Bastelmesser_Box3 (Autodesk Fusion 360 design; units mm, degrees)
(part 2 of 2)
sketch "Skizze4" plane through (0, 0, 22) normal (0, 0, -1) x axis (1, 0, 0)
  line L1 (-74.6486, 4.3998) -> (74.6267, 4.3982)
  line L2 (-75.4335, 4.1218) -> (-74.6486, 4.3998)
  line L3 (-76.2604, 3.6728) -> (-75.4335, 4.1218)
  line L4 (-77.0079, 3.099) -> (-76.2604, 3.6728)
  line L5 (-77.6547, 2.4173) -> (-77.0079, 3.099)
  line L6 (-78.1871, 1.6426) -> (-77.6547, 2.4173)
  line L7 (-78.5922, 0.7932) -> (-78.1871, 1.6426)
  line L8 (-78.8596, -0.1097) -> (-78.5922, 0.7932)
  line L9 (-78.9823, -1.0422) -> (-78.8596, -0.1097)
  line L10 (-78.986, -28.0662) -> (-78.9823, -1.0422)
  line L11 (-78.9923, -28.0662) -> (-78.986, -28.0662)
  line L12 (-78.9946, -45.3556) -> (-78.9923, -28.0662)
  line L13 (-78.9578, -45.9816) -> (-78.9946, -45.3556)
  line L14 (-78.7863, -46.9071) -> (-78.9578, -45.9816)
  line L15 (-78.4721, -47.7945) -> (-78.7863, -46.9071)
  line L16 (-78.0231, -48.6214) -> (-78.4721, -47.7945)
  line L17 (-77.4515, -49.3665) -> (-78.0231, -48.6214)
  line L18 (-76.7688, -50.0146) -> (-77.4515, -49.3665)
  line L19 (-75.9928, -50.5481) -> (-76.7688, -50.0146)
  line L20 (-75.1435, -50.9532) -> (-75.9928, -50.5481)
  line L21 (-74.2406, -51.2206) -> (-75.1435, -50.9532)
  line L22 (-73.3081, -51.3433) -> (-74.2406, -51.2206)
  line L23 (73.0054, -51.3556) -> (-73.3081, -51.3433)
  line L24 (73.6314, -51.3188) -> (73.0054, -51.3556)
  line L25 (74.5569, -51.1473) -> (73.6314, -51.3188)
  line L26 (75.4442, -50.8331) -> (74.5569, -51.1473)
  line L27 (76.2712, -50.3841) -> (75.4442, -50.8331)
  line L28 (77.0186, -49.8103) -> (76.2712, -50.3841)
  line L29 (77.6654, -49.1285) -> (77.0186, -49.8103)
  line L30 (78.1978, -48.3538) -> (77.6654, -49.1285)
  line L31 (78.603, -47.5045) -> (78.1978, -48.3538)
  line L32 (78.8704, -46.6016) -> (78.603, -47.5045)
  line L33 (78.9931, -45.6691) -> (78.8704, -46.6016)
  line L34 (78.9954, -28.0662) -> (78.9931, -45.6691)
  line L35 (79.0018, -28.0662) -> (78.9954, -28.0662)
  line L36 (79.0054, -1.3556) -> (79.0018, -28.0662)
  line L37 (78.9685, -0.7297) -> (79.0054, -1.3556)
  line L38 (78.797, 0.1959) -> (78.9685, -0.7297)
  line L39 (78.4828, 1.0832) -> (78.797, 0.1959)
  line L40 (78.0338, 1.9102) -> (78.4828, 1.0832)
  line L41 (77.4622, 2.6553) -> (78.0338, 1.9102)
  line L42 (76.7795, 3.3034) -> (77.4622, 2.6553)
  line L43 (76.0036, 3.8368) -> (76.7795, 3.3034)
  line L44 (75.1543, 4.242) -> (76.0036, 3.8368)
  line L45 (74.6267, 4.3982) -> (75.1543, 4.242)
  line L46 (73.2524, 2.3821) -> (4.5274, 2.3878)
  line L47 (76.7518, -28.0662) -> (76.7554, -1.3636)
  line L48 (76.7454, -28.0662) -> (76.7518, -28.0662)
  line L49 (76.7431, -45.6026) -> (76.7454, -28.0662)
  line L50 (-73.2416, -49.0933) -> (72.9975, -49.1056)
  line L51 (-76.7423, -28.0662) -> (-76.7446, -45.3477)
  line L52 (-76.736, -28.0662) -> (-76.7423, -28.0662)
  line L53 (-76.7323, -1.1087) -> (-76.736, -28.0662)
  line L54 (-4.4801, 2.3886) -> (-72.9867, 2.3944)
  line L55 (-4.6241, 3.499) -> (-4.6241, 2.399)
  line L56 (4.6759, 3.4989) -> (-4.6241, 3.499)
  line L57 (4.6759, 2.3989) -> (4.6759, 3.4989)
  line L58 (3.6759, 1.3989) -> (3.6759, 0.4365)
  line L59 (4.6759, 3.4989) -> (4.6759, 2.3989)
  line L60 (-4.6241, 3.499) -> (4.6759, 3.4989)
  line L61 (-4.6241, 2.399) -> (-4.6241, 3.499)
  line L62 (-3.6241, 0.4365) -> (-3.6241, 1.399)
  line L63 (-76.111, 2.359) -> (-75.7926, 2.6225)
  line L64 (-76.8834, 1.5652) -> (-76.7298, 1.7396)
  line L65 (-77.2915, 0.9221) -> (-76.8834, 1.5652)
  line L66 (-77.5943, 0.2226) -> (-77.2915, 0.9221)
  line L67 (-77.7838, -0.516) -> (-77.5943, 0.2226)
  line L68 (-77.8485, -1.2003) -> (-77.7838, -0.516)
  line L69 (-77.8485, -4.8869) -> (-77.8485, -1.2003)
  line L70 (-76.7485, -4.8869) -> (-77.8485, -4.8869)
  line L71 (-74.202, -3.8821) -> (-75.7516, -3.8869)
  line L72 (-70.4875, 1.3992) -> (-70.4868, -0.1536)
  line L73 (-69.4875, 3.4997) -> (-69.4875, 2.3997)
  line L74 (-73.0871, 3.4997) -> (-69.4875, 3.4997)
  line L75 (-73.6968, 3.4545) -> (-73.0871, 3.4997)
  line L76 (-74.4278, 3.2911) -> (-73.6968, 3.4545)
  line L77 (-75.1365, 3.0105) -> (-74.4278, 3.2911)
  line L78 (-75.7926, 2.6225) -> (-75.1365, 3.0105)
  line L79 (75.7523, -3.8661) -> (74.2621, -3.8625)
  line L80 (77.8499, -4.8661) -> (76.7499, -4.8661)
  line L81 (77.85, -1.2631) -> (77.8499, -4.8661)
  line L82 (77.8047, -0.6535) -> (77.85, -1.2631)
  line L83 (77.6414, 0.0776) -> (77.8047, -0.6535)
  line L84 (77.3608, 0.7863) -> (77.6414, 0.0776)
  line L85 (76.9729, 1.442) -> (77.3608, 0.7863)
  line L86 (76.8724, 1.5635) -> (76.9729, 1.442)
  line L87 (75.9161, 2.5327) -> (76.2518, 2.2367)
  line L88 (75.2724, 2.9413) -> (75.9161, 2.5327)
  line L89 (74.5729, 3.244) -> (75.2724, 2.9413)
  line L90 (73.8343, 3.4336) -> (74.5729, 3.244)
  line L91 (73.1499, 3.4982) -> (73.8343, 3.4336)
  line L92 (69.6287, 3.4982) -> (73.1499, 3.4982)
  line L93 (69.6287, 2.3982) -> (69.6287, 3.4982)
  line L94 (70.6209, -0.1946) -> (70.6287, 1.3933)
  arc A1 centre (4.6759, 1.3989) radius 1 clockwise from (4.5274, 2.3878) to (4.6759, 2.3989)
  arc A2 centre (73.0018, -1.3631) radius 3.7536 clockwise from (73.2524, 2.3821) to (76.7554, -1.3636)
  arc A3 centre (72.9978, -45.352) radius 3.7537 clockwise from (76.7431, -45.6026) to (72.9975, -49.1056)
  arc A4 centre (-72.9911, -45.3482) radius 3.7536 clockwise from (-73.2416, -49.0933) to (-76.7446, -45.3477)
  arc A5 centre (-72.987, -1.3593) radius 3.7537 clockwise from (-76.7323, -1.1087) to (-72.9867, 2.3944)
  arc A6 centre (-4.6241, 1.399) radius 1 clockwise from (-4.6241, 2.399) to (-4.4801, 2.3886)
  circle C1 centre (0.0259, 0.4365) radius 3.05
  arc A7 centre (4.6759, 1.3989) radius 1 clockwise from (3.6759, 1.3989) to (4.6759, 2.3989)
  arc A8 centre (-4.6241, 1.399) radius 1 clockwise from (-4.6241, 2.399) to (-3.6241, 1.399)
  arc A9 centre (0.0259, 0.4365) radius 3.65 clockwise from (3.6759, 0.4365) to (-3.6241, 0.4365)
  arc A10 centre (-74.2135, -0.1554) radius 3.15 clockwise from (-76.111, 2.359) to (-76.7298, 1.7396)
  arc A11 centre (-75.7485, -4.8869) radius 1 clockwise from (-76.7485, -4.8869) to (-75.7516, -3.8869)
  arc A12 centre (-74.2135, -0.1554) radius 3.7267 clockwise from (-70.4868, -0.1536) to (-74.202, -3.8821)
  arc A13 centre (-69.4875, 1.3997) radius 1 clockwise from (-70.4875, 1.3992) to (-69.4875, 2.3997)
  arc A14 centre (75.7499, -4.8661) radius 1 clockwise from (75.7523, -3.8661) to (76.7499, -4.8661)
  arc A15 centre (74.2708, -0.2125) radius 3.15 clockwise from (76.8724, 1.5635) to (76.2518, 2.2367)
  arc A16 centre (69.6287, 1.3982) radius 1 clockwise from (69.6287, 2.3982) to (70.6287, 1.3933)
  arc A17 centre (74.2708, -0.2125) radius 3.65 clockwise from (74.2621, -3.8625) to (70.6209, -0.1946)
  circle C2 centre (74.2708, -0.2125) radius 3.15
  circle C3 centre (-74.2135, -0.1554) radius 3.15
  point P115 (76.8724, 1.5635)
  point P83 (-76.111, 2.359)
  concentric A15 C2
  coincident P115 C2
  concentric A10 C3
  coincident P83 C3
extrude "Extrusion2" cut sketch "Skizze4" profile of L46 L47 L48 L49 A3 L50 A4 L51 L52 L53 A5 L54 L58 A7 A8 L62 A9 A10 A11 L71 A12 L72 A13 L79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 against normal blind 1.213
extrude "Extrusion3" cut of existing geometry blind -2.287
extrude "Extrusion4" cut sketch "Skizze4" profile of L46 A2 L47 A15 C2 against normal blind 3.452
combine "Kombinieren2"
extrude "Extrusion11" new body of existing geometry blind 3.5
extrude "Extrusion12" cut of existing geometry blind -2.05
extrude "Extrusion13" new body of existing geometry blind 3.452
extrude "Extrusion14" new body of existing geometry blind 3.5
combine "Kombinieren2"
extrude "Extrusion15" cut of existing geometry blind -2.05
extrude "Extrusion16" new body of existing geometry blind 3.5
delete_face "Fläche löschen3"
extrude "Extrusion17" new body of existing geometry blind 3.5
combine "Kombinieren3"
extrude "Extrusion18" cut of existing geometry blind -2.05
fillet "Abrundung1" radius 2
combine "Kombinieren3"
extrude "Extrusion5" cut of existing geometry blind -0.006
sketch "Skizze5" plane through (0, 0, 25.5) normal (0, 0, -1) x axis (1, 0, 0)
  line L1 (74.755, -3.8637) -> (74.7518, -28.0662)
  line L2 (74.2621, -3.8625) -> (74.755, -3.8637)
  line L3 (70.6237, 0.3823) -> (70.6209, -0.1946)
  line L4 (3.6755, 0.3879) -> (70.6237, 0.3823)
  line L5 (-70.487, 0.3942) -> (-3.6238, 0.3885)
  line L6 (-70.4868, -0.1536) -> (-70.487, 0.3942)
  line L7 (-74.739, -3.8838) -> (-74.202, -3.8821)
  line L8 (-74.7446, -45.3479) -> (-74.739, -3.8838)
  line L9 (72.9976, -47.1056) -> (-73.1622, -47.0933)
  line L10 (74.7454, -28.0662) -> (74.7431, -45.523)
  line L11 (74.7518, -28.0662) -> (74.7454, -28.0662)
  line L12 (-0.0823, -47.0995) -> (0, 0)
  arc A1 centre (74.2708, -0.2125) radius 3.65 clockwise from (74.2621, -3.8625) to (70.6209, -0.1946)
  arc A2 centre (0.0259, 0.4365) radius 3.65 clockwise from (3.6755, 0.3879) to (-3.6238, 0.3885)
  arc A3 centre (-74.2135, -0.1554) radius 3.7267 clockwise from (-70.4868, -0.1536) to (-74.202, -3.8821)
  arc A4 centre (-72.9911, -45.3482) radius 1.7535 clockwise from (-73.1622, -47.0933) to (-74.7446, -45.3479)
  arc A5 centre (72.9978, -45.352) radius 1.7537 clockwise from (74.7431, -45.523) to (72.9976, -47.1056)
  circle C1 centre (-0.0411, -23.5497) radius 3.1
  circle C2 centre (-0.0411, -23.5497) radius 4
  point P1 (0, 0)
  point P23 (0, 0)
  point P24 (-0.0823, -47.0995)
  point P25 (-0.0411, -23.5497)
  point P27 (-0.0411, -23.5497)
  coincident P1 P23
  midpoint L9 P24
  midpoint L12 P25
  coincident P25 P27
  concentric C1 C2
  dimension "d144" diameter C1 = 6.2
  dimension "d151" diameter C2 = 8
extrude "Extrusion6" cut sketch "Skizze5" profile of C1 against normal blind 1.9
rectangular_pattern "R-Anordnung1" uSpaceDistance 65.27 vSpaceDistance 0
extrude "Extrusion19" add sketch "Skizze5" profile of C1 C2 along normal blind 0.2
rectangular_pattern "R-Anordnung1" uSpaceDistance 65.269 vSpaceDistance 0
extrude "Extrusion7" cut of existing geometry blind -0.2
extrude "Extrusion20" cut of existing geometry blind -0.2
extrude "Extrusion8" cut of existing geometry blind -0.2
extrude "Extrusion21" cut of existing geometry blind -0.1
extrude "Extrusion9" cut of existing geometry blind -0.1
combine "Kombinieren4"
combine "Kombinieren5"
sketch "Skizze6" plane through (0, -4.399, 0) normal (0, -1, 0) x axis (1, 0, 0)
  line L1 (74.6267, 22.2) -> (-74.6486, 22.2)
  line L2 (74.6267, 28) -> (74.6267, 22.2)
  line L3 (-74.6486, 28) -> (74.6267, 28)
  line L4 (-74.6486, 22.2) -> (-74.6486, 28)
  line L5 (-7.511, 23.7) -> (7.489, 23.7)
  line L6 (-7.511, 20.7) -> (-7.511, 23.7)
  line L7 (7.489, 20.7) -> (-7.511, 20.7)
  line L8 (7.489, 23.7) -> (7.489, 20.7)
  line L9 (-7.511, 20.7) -> (7.489, 23.7)
  line L10 (7.489, 20.7) -> (-7.511, 23.7)
  point P6 (-0.011, 22.2)
  point P7 (0.8094, 22.2)
  point P12 (-0.011, 22.2)
  point P10 (-7.511, 20.7)
  point P11 (7.489, 20.7)
  point P9 (-7.511, 23.7)
  midpoint L1 P6
  coincident L1 P7
  horizontal L5
  perpendicular L5 L6
  parallel L5 L7
  parallel L6 L8
  coincident L9 P12
  coincident L10 P12
  coincident P6 P12
  dimension "d168" distance P10 P11 = 15
  dimension "d169" distance P9 P10 = 3
extrude "Extrusion10" add sketch "Skizze6" profile of L1 L5 L6 L7 L8 along normal blind 1.5
fillet "Abrundung2" radius 1
fillet "Abrundung3" radius 0.5
sketch "Skizze7" plane through (0, 0, 28) normal (0, 0, 1) x axis (-1, 0, 0)
  line L1 (-78.9931, -45.6691) -> (-78.9954, -28.0662)
  line L2 (-78.8704, -46.6016) -> (-78.9931, -45.6691)
  line L3 (-78.603, -47.5045) -> (-78.8704, -46.6016)
  line L4 (-78.1978, -48.3538) -> (-78.603, -47.5045)
  line L5 (-77.6654, -49.1285) -> (-78.1978, -48.3538)
  line L6 (-77.0186, -49.8103) -> (-77.6654, -49.1285)
  line L7 (-76.2712, -50.3841) -> (-77.0186, -49.8103)
  line L8 (-75.4442, -50.8331) -> (-76.2712, -50.3841)
  line L9 (-74.5569, -51.1473) -> (-75.4442, -50.8331)
  line L10 (-73.6314, -51.3188) -> (-74.5569, -51.1473)
  line L11 (-73.0054, -51.3556) -> (-73.6314, -51.3188)
  line L12 (73.3081, -51.3433) -> (-73.0054, -51.3556)
  line L13 (74.2406, -51.2206) -> (73.3081, -51.3433)
  line L14 (75.1435, -50.9532) -> (74.2406, -51.2206)
  line L15 (75.9928, -50.5481) -> (75.1435, -50.9532)
  line L16 (76.7688, -50.0146) -> (75.9928, -50.5481)
  line L17 (77.4515, -49.3665) -> (76.7688, -50.0146)
  line L18 (78.0231, -48.6214) -> (77.4515, -49.3665)
  line L19 (78.4721, -47.7945) -> (78.0231, -48.6214)
  line L20 (78.7863, -46.9071) -> (78.4721, -47.7945)
  line L21 (78.9578, -45.9816) -> (78.7863, -46.9071)
  line L22 (78.9946, -45.3556) -> (78.9578, -45.9816)
  line L23 (78.9923, -28.0662) -> (78.9946, -45.3556)
  line L24 (78.9823, -1.0422) -> (78.986, -28.0662)
  line L25 (78.8596, -0.1097) -> (78.9823, -1.0422)
  line L26 (78.5922, 0.7932) -> (78.8596, -0.1097)
  line L27 (78.1871, 1.6426) -> (78.5922, 0.7932)
  line L28 (77.6547, 2.4173) -> (78.1871, 1.6426)
  line L29 (77.0079, 3.099) -> (77.6547, 2.4173)
  line L30 (76.2604, 3.6728) -> (77.0079, 3.099)
  line L31 (75.4335, 4.1218) -> (76.2604, 3.6728)
  line L32 (74.6486, 4.3998) -> (75.4335, 4.1218)
  line L33 (-74.6267, 4.3982) -> (74.6486, 4.3998)
  line L34 (-75.1543, 4.242) -> (-74.6267, 4.3982)
  line L35 (-76.0036, 3.8368) -> (-75.1543, 4.242)
  line L36 (-76.7795, 3.3034) -> (-76.0036, 3.8368)
  line L37 (-77.4622, 2.6553) -> (-76.7795, 3.3034)
  line L38 (-78.0338, 1.9102) -> (-77.4622, 2.6553)
  line L39 (-78.4828, 1.0832) -> (-78.0338, 1.9102)
  line L40 (-78.797, 0.1959) -> (-78.4828, 1.0832)
  line L41 (-78.9685, -0.7297) -> (-78.797, 0.1959)
  line L42 (-79.0054, -1.3556) -> (-78.9685, -0.7297)
  line L43 (-79.0018, -28.0662) -> (-79.0054, -1.3556)
  curve K1
  curve K2
  curve K3
  curve K4
  dimension "d176" Text1-Height = 7
extrude "Extrusion11" new body sketch "Skizze7" along normal blind 0.4
move "Verschieben6"
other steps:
split "Teilen2" bodies "box_W150xD95xH20 (2)"
split "Teilen3" bodies "box_W150xD95xH20 (2) (1)"
extrude "Extrusion1" cut of existing geometry blind -3.5
create_component "Komponente erstellen1"
create_component "Komponente erstellen2"
remove_body "Körper entfernen1"
remove_body "Körper entfernen2"
remove_body "Körper entfernen3"
remove_body "Körper entfernen4"
remove_body "Körper entfernen5"
remove_body "Körper entfernen6"
remove_body "Körper entfernen7"
remove_body "Körper entfernen8"
remove_body "Körper entfernen9"
remove_body "Körper entfernen10"
remove_body "Körper entfernen11"
remove_body "Körper entfernen12"
remove_body "Körper entfernen13"
remove_body "Körper entfernen14"
remove_body "Körper entfernen15"
remove_body "Körper entfernen16"
remove_body "Körper entfernen17"
remove_body "Körper entfernen18"
remove_body "Körper entfernen19"
remove_body "Körper entfernen20"
remove_body "Körper entfernen21"
remove_body "Körper entfernen22"
remove_body "Körper entfernen23"
remove_body "Körper entfernen24"
remove_body "Körper entfernen25"
remove_body "Körper entfernen26"
remove_body "Körper entfernen27"
remove_body "Körper entfernen28"
remove_body "Körper entfernen29"
remove_body "Körper entfernen30"
remove_body "Körper entfernen31"
remove_body "Körper entfernen32"
remove_body "Körper entfernen33"
remove_body "Körper entfernen34"
remove_body "Körper entfernen35"
remove_body "Körper entfernen36"
remove_body "Körper entfernen37"
remove_body "Körper entfernen38"
remove_body "Körper entfernen39"
remove_body "Körper entfernen40"
remove_body "Körper entfernen41"
remove_body "Körper entfernen42"
remove_body "Körper entfernen43"
remove_body "Körper entfernen44"
remove_body "Körper entfernen45"
remove_body "Körper entfernen46"
remove_body "Körper entfernen47"
remove_body "Körper entfernen48"
remove_body "Körper entfernen49"
remove_body "Körper entfernen50"
remove_body "Körper entfernen51"
remove_body "Körper entfernen52"
remove_body "Körper entfernen53"
remove_body "Körper entfernen54"
remove_body "Körper entfernen55"
remove_body "Körper entfernen56"
remove_body "Körper entfernen57"
remove_body "Körper entfernen58"
remove_body "Körper entfernen59"
named bodies: "lid_W150xD95xH20", "box_W150xD95xH20", "lid_W150xD95xH20 (1)", "box_W150xD95xH20 (2)", "lid_W150xD95xH20 (1) (1)", "box_W150xD95xH20 (2) (1)", "box_W150xD95xH20 (1)", "box_W150xD95xH20 (3)", "box_W150xD95xH20 (4)", "box_W150xD95xH20 (5)", "box_W150xD95xH20 (6)", "box_W150xD95xH20 (7)", "box_W150xD95xH20 (8)", "box_W150xD95xH20 (9)", "box_W150xD95xH20 (10)", "box_W150xD95xH20 (11)", "box_W150xD95xH20 (12)", "box_W150xD95xH20 (13)", "box_W150xD95xH20 (14)", "lid_W150xD95xH20 (2)"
